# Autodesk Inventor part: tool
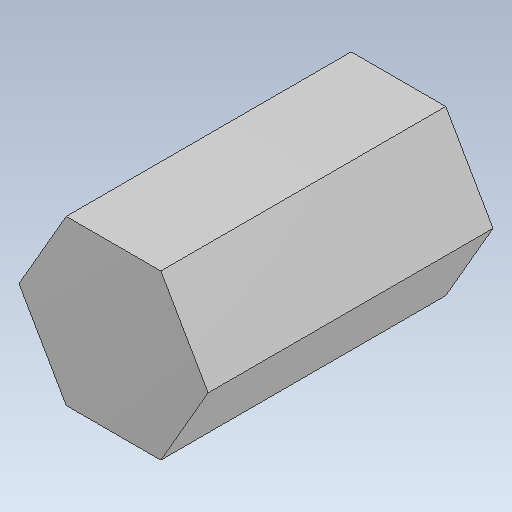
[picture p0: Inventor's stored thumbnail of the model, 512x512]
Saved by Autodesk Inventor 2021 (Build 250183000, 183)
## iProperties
Created: 2026-10
Part Number: tool
Material: Steel
Document SubType Name: Modeling
Designer: hp
Density: 7.85 g/cm^3
Appearance: Default
Author: hp
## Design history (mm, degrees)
feature "Body1"
body "Solid1"
